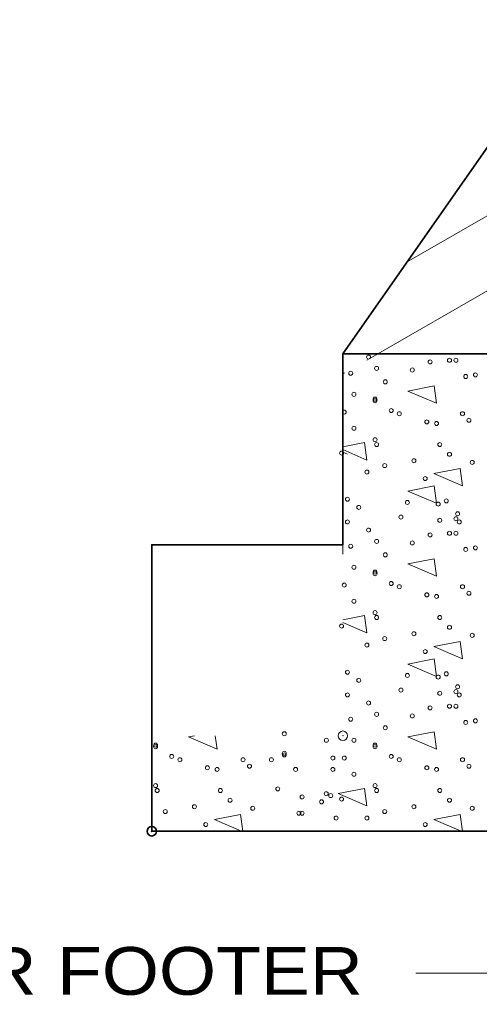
# Model space of a CAD drawing. Extents: x -43.06 to -36.2, y -1.41 to 7.25.
# Drawn here: x -37.83 to -37.252, y 2.28 to 3.506 of the extents above; entities that cross this region are included whole.
import ezdxf
from ezdxf.enums import TextEntityAlignment as Align

# ---------------------------------------------------------------- set-up
doc = ezdxf.new("R2010")
doc.units = 0
doc.header["$LTSCALE"] = 0.024
doc.header["$PDMODE"] = 32
doc.header["$PDSIZE"] = 0.012
for name, color, linetype, lineweight in [('1', 7, 'Continuous', 35), ('10', 7, 'Continuous', 13), ('12', 7, 'Continuous', 53), ('6', 7, 'Continuous', 13)]:
    doc.layers.add(name, color=color, linetype=linetype, lineweight=lineweight)

msp = doc.modelspace()

# ---------------------------------------------------------------- linework, layer by layer
at = {"layer": '1'}
msp.add_line((-37.66358, 2.48633), (-36.22325, 2.48633), dxfattribs=at)
for points in [[(-37.20258, 3.40183), (-37.42342, 3.08633), (-37.42342, 2.84633)], [(-37.42342, 3.08633), (-36.94342, 3.08633), (-36.94342, 2.96633)], [(-37.66358, 2.48633), (-37.66358, 2.84633), (-37.42342, 2.84633)]]:
    msp.add_lwpolyline(points, dxfattribs=at)
msp.add_point((-37.66358, 2.48633), dxfattribs=at)
at = {"layer": '10'}
msp.add_line((-37.33192, 2.308), (-37.22992, 2.308), dxfattribs=at)
at = {"layer": '6'}
for p, q in [((-37.34258, 3.202), (-36.81342, 3.50633)), ((-37.39342, 3.07833), (-36.81342, 3.412)), ((-37.42342, 3.061), (-37.42142, 3.06217)), ((-37.42342, 3.004), (-37.42325, 3.00417)), ((-37.41742, 2.96033), (-37.42342, 2.96283)), ((-37.42342, 2.83433), (-37.42342, 2.84633)), ((-37.61758, 2.60483), (-37.60992, 2.60633)), ((-37.55075, 2.48633), (-37.58492, 2.501)), ((-37.27492, 2.48633), (-37.30908, 2.501))]:
    msp.add_line(p, q, dxfattribs=at)
for points in [[(-37.34175, 3.0395), (-37.30858, 3.046), (-37.30575, 3.02417)], [(-37.30908, 2.93567), (-37.27608, 2.94217), (-37.27325, 2.92033)], [(-37.34175, 2.91383), (-37.30858, 2.92033), (-37.30575, 2.8985)], [(-37.34175, 2.82217), (-37.30858, 2.82867), (-37.30575, 2.80683)], [(-37.30908, 2.71833), (-37.27608, 2.72483), (-37.27325, 2.703)], [(-37.34175, 2.6965), (-37.30858, 2.703), (-37.30575, 2.681)], [(-37.34175, 2.60483), (-37.30858, 2.61133), (-37.30575, 2.5895)], [(-37.42925, 2.53367), (-37.39625, 2.54017), (-37.39342, 2.51817)]]:
    msp.add_lwpolyline(points, close=True, dxfattribs=at)
for points in [[(-37.42342, 2.9695), (-37.39625, 2.97483), (-37.39342, 2.95283), (-37.42342, 2.96583)], [(-37.42342, 2.75217), (-37.39625, 2.7575), (-37.39342, 2.7355), (-37.42342, 2.7485)], [(-37.58375, 2.60633), (-37.58158, 2.5895), (-37.61758, 2.60483)], [(-37.58492, 2.501), (-37.55192, 2.5075), (-37.54908, 2.48633)], [(-37.30908, 2.501), (-37.27608, 2.5075), (-37.27325, 2.48633)]]:
    msp.add_lwpolyline(points, dxfattribs=at)
for centre in [(-37.39118, 3.08221), (-37.3138, 3.07609), (-37.2894, 3.07813), (-37.28124, 3.07813), (-37.38102, 3.06797), (-37.33621, 3.06593), (-37.41358, 3.06185), (-37.26904, 3.05777), (-37.2568, 3.05981), (-37.37009, 3.05105), (-37.4095, 3.03536), (-37.38302, 3.02928), (-37.38302, 3.02724), (-37.36269, 3.015), (-37.4217, 3.013), (-37.35249, 3.01096), (-37.27308, 3.01096), (-37.26496, 3.0028), (-37.4095, 2.99264), (-37.31789, 3.00076), (-37.30568, 2.99872), (-37.38302, 2.97836), (-37.38102, 2.97227), (-37.3016, 2.97227), (-37.42506, 2.96147), (-37.2894, 2.96003), (-37.37081, 2.94579), (-37.33417, 2.95191), (-37.26088, 2.94987), (-37.39322, 2.93767), (-37.31993, 2.92951), (-37.41766, 2.90354), (-37.40338, 2.89334), (-37.34233, 2.89946), (-37.30364, 2.89742), (-37.29344, 2.9015), (-37.35045, 2.88114), (-37.2792, 2.88522), (-37.41766, 2.87502), (-37.3016, 2.87706), (-37.28124, 2.8791), (-37.27716, 2.87502), (-37.39118, 2.86486), (-37.3138, 2.85874), (-37.2894, 2.86078), (-37.28124, 2.86078), (-37.41358, 2.84449), (-37.38102, 2.85061), (-37.33621, 2.84857), (-37.37009, 2.83369), (-37.26904, 2.84041), (-37.2568, 2.84245), (-37.4095, 2.81801), (-37.38302, 2.81193), (-37.38302, 2.80989), (-37.4217, 2.79565), (-37.36269, 2.79765), (-37.35249, 2.79361), (-37.27308, 2.79361), (-37.31789, 2.7834), (-37.30568, 2.78136), (-37.26496, 2.78544), (-37.4095, 2.77528), (-37.38302, 2.761), (-37.38102, 2.75492), (-37.3016, 2.75492), (-37.42506, 2.74412), (-37.33417, 2.73456), (-37.2894, 2.74268), (-37.26088, 2.73252), (-37.39322, 2.72031), (-37.37081, 2.72844), (-37.31993, 2.71215), (-37.41766, 2.68619), (-37.29344, 2.68415), (-37.40338, 2.67599), (-37.34233, 2.68211), (-37.30364, 2.68007), (-37.35045, 2.66378), (-37.3016, 2.6597), (-37.28124, 2.66174), (-37.2792, 2.66787), (-37.41766, 2.65766), (-37.39118, 2.6475), (-37.27716, 2.65766), (-37.3138, 2.64138), (-37.2894, 2.64342), (-37.28124, 2.64342), (-37.41358, 2.62714), (-37.38102, 2.63326), (-37.33621, 2.63122), (-37.26904, 2.62306), (-37.2568, 2.6251), (-37.37009, 2.61634), (-37.49703, 2.60882), (-37.44411, 2.60065), (-37.4095, 2.60065), (-37.65882, 2.59457), (-37.65882, 2.59253), (-37.38302, 2.59457), (-37.38302, 2.59253), (-37.6385, 2.58029), (-37.62829, 2.57625), (-37.54888, 2.57625), (-37.51332, 2.57625), (-37.49703, 2.58437), (-37.49703, 2.58233), (-37.43598, 2.57829), (-37.4217, 2.57829), (-37.36269, 2.58029), (-37.35249, 2.57625), (-37.27308, 2.57625), (-37.59369, 2.56605), (-37.58149, 2.56401), (-37.54076, 2.56809), (-37.48279, 2.56401), (-37.43598, 2.56401), (-37.31789, 2.56605), (-37.30568, 2.56401), (-37.26496, 2.56809), (-37.4095, 2.55793), (-37.65882, 2.54365), (-37.65682, 2.53756), (-37.57741, 2.53756), (-37.5052, 2.5396), (-37.38302, 2.54365), (-37.38102, 2.53756), (-37.3016, 2.53756), (-37.5652, 2.52532), (-37.47467, 2.5294), (-37.44435, 2.53356), (-37.4387, 2.53112), (-37.42506, 2.52676), (-37.2894, 2.52532), (-37.60997, 2.5172), (-37.53668, 2.51516), (-37.45023, 2.52332), (-37.33417, 2.5172), (-37.26088, 2.51516), (-37.64662, 2.51108), (-37.47871, 2.50904), (-37.47467, 2.50904), (-37.4319, 2.50296), (-37.39322, 2.50296), (-37.37081, 2.51108), (-37.59573, 2.4948), (-37.31993, 2.4948)]:
    msp.add_circle(centre, 0.00252, dxfattribs=at)
msp.add_point((-37.42342, 2.60633), dxfattribs=at)

# ---------------------------------------------------------------- texts
at = {"layer": '12', "width": 1.15}
msp.add_text('BARRIER FOOTER', height=0.06001, dxfattribs=at).set_placement((-37.80842, 2.28083), align=Align.CENTER)

doc.saveas('drawing.dxf')
